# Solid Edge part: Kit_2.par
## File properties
Author: bmolnar
Last saved by: bmolnar
Revision: 76
Sűrűség: 0,000 kg/m^3
Pontosság: 0,990
Username: bmolnar
Dokumentum tartalom típus: 0
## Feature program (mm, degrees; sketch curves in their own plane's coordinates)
base feature "unnamed BaseFeature 1"
sketch for "Furat_1" plane through (-20.15, 0, 96.65) normal (1, 0, 0) x-axis (0, 1, 0)
  hole centre (0, -15.15) bore radius 2.067
hole "Furat_1" nominal diameter 5 finite  StartChamferOffset = 0.6 mm; StartChamferAngle = 45 deg
sketch for "Furat_2" plane through (-13, -13, 83.9) normal (0, 0, 1) x-axis (0, 1, 0)
  hole centre (0, 0) bore radius 2.067
hole "Furat_2" nominal diameter 5
sketch for "unnamed Hole 1" plane through (-13, -13, 83.9) normal (0, 0, 1) x-axis (0, 1, 0)
  hole centre (26, 0) bore radius 2.067
hole "unnamed Hole 1"
sketch for "unnamed Hole 2" plane through (-13, -13, 83.9) normal (0, 0, 1) x-axis (0, 1, 0)
  hole centre (26, -26) bore radius 2.067
hole "unnamed Hole 2"
sketch for "unnamed Hole 3" plane through (-13, -13, 83.9) normal (0, 0, 1) x-axis (0, 1, 0)
  hole centre (0, -26) bore radius 2.067
hole "unnamed Hole 3"
pattern "unnamed Pattern 1" of "Furat_2", "unnamed Hole 1", "unnamed Hole 2", "unnamed Hole 3"
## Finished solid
Body 1: solid body, 265 faces, 630 edges, 376 vertices, 3 internal voids.
  Faces by surface: plane 132, cylinder 56, swept 42, cone 26, torus 9
  Edges by curve: line 381, circle 155, spline 88, curve on surface 5, ellipse 1
Bounding box of the edges (mm; curved faces can reach further): 40.300 x 40.300 x 12.500, from (-20.15, -20.15, 76.5) to (20.15, 20.15, 89).
Cylindrical faces by radius (mm): R0.2 x18, R0.4246 x1, R0.4865 x1, R2.067 x5, R3.75 x2, R4 x4, R4.1 x12, R5.24 x1, R5.45 x2, R5.55 x2, R5.7 x1, R6 x1, R6.92 x1, R7 x1, R13.75 x4
Conical faces (half-angle, radius in mm at the cone's reference point): 0.5 deg R5 x4, 3 deg R6.96 x1, 7 deg R6.4156 x1, 14 deg R5.12 x1, 14 deg R5.3801 x1, 17 deg R5.12 x1, 23 deg R5.7369 x1, 42.5 deg R5.1096 x1, 45 deg R2.317 x2, 45 deg R2.367 x2, 45 deg R2.667 x1, 45 deg R4.25 x2, 45 deg R5.3 x2, 45 deg R5.35 x2, 45 deg R5.85 x1, 84 deg R5.4096 x1, 85 deg R6.73 x1, 87 deg R5.1371 x1
Toroidal faces (ring radius, tube radius in mm): R3.8 r0.2 x2, R4.4 r0.4 x2, R5.6606 r0.18 x1, R6.1131 r0.26 x1, R6.72 r0.2 x1, R9.4957 r0.5 x1, R11.0043 r0.5 x1
Planar faces by outward normal: +x 5, +y 16, +z 17, -x 7, -y 13, -z 5, oblique 69
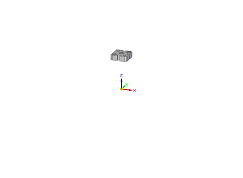
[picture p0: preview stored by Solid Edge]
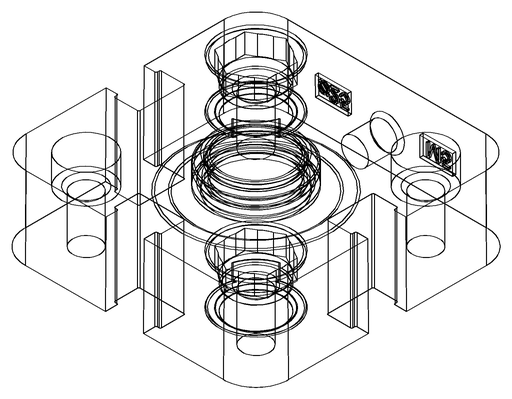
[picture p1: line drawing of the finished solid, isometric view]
